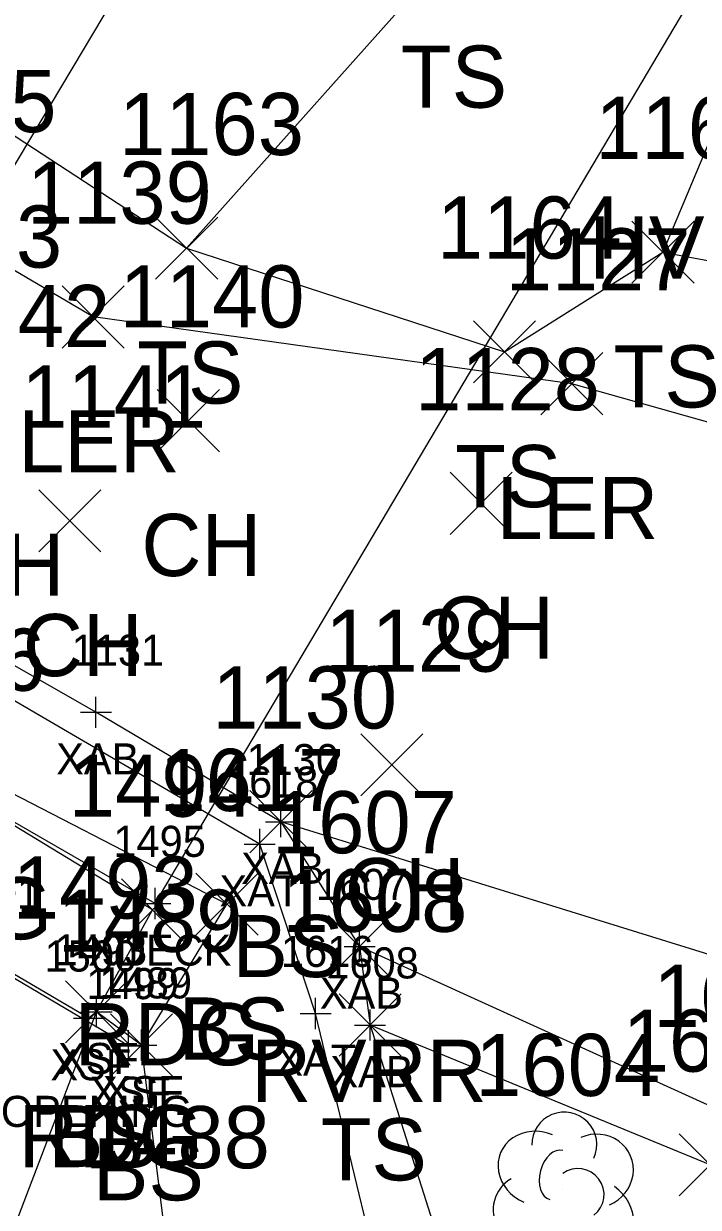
# Model space of a CAD drawing. Extents: x 1600281 to 1602254, y 862855 to 863227.
# Drawn here: x 1602044.06 to 1602065.77, y 863032.19 to 863070.29 of the extents above; entities that cross this region are included whole.
import ezdxf

# ---------------------------------------------------------------- set-up
doc = ezdxf.new("R2010")
doc.units = 0
for name, color, linetype in [('B_A', 7, 'Continuous'), ('B_C', 7, 'Continuous'), ('B_I', 7, 'Continuous'), ('B_TIC', 7, 'Continuous'), ('BDEFAULT', 7, 'Continuous'), ('BELB', 7, 'Continuous'), ('BSUBM', 7, 'Continuous'), ('C_A', 7, 'Continuous'), ('L_A', 7, 'Continuous'), ('L_I', 7, 'Continuous'), ('L_TIC', 7, 'Continuous'), ('LARO', 7, 'Continuous'), ('LAWE', 7, 'Continuous'), ('LELB', 7, 'Continuous'), ('LTD', 7, 'Continuous'), ('P_A', 7, 'Continuous'), ('P_I', 7, 'Continuous'), ('P_TIC', 7, 'Continuous'), ('PEU', 7, 'Continuous')]:
    doc.layers.add(name, color=color, linetype=linetype)

msp = doc.modelspace()

# ---------------------------------------------------------------- linework, layer by layer
at = {"layer": 'B_TIC'}
for p, q in [((1602046.387, 863048.124), (1602046.463, 863048.124)), ((1602052.341, 863044.601), (1602052.417, 863044.601)), ((1602052.341, 863044.601), (1602052.417, 863044.601)), ((1602051.658, 863043.876), (1602051.734, 863043.876)), ((1602048.296, 863041.97), (1602048.371, 863041.97)), ((1602048.296, 863041.97), (1602048.371, 863041.97)), ((1602054.871, 863040.585), (1602054.947, 863040.585)), ((1602046.162, 863038.279), (1602046.238, 863038.279)), ((1602046.405, 863038.482), (1602046.481, 863038.482)), ((1602053.456, 863038.428), (1602053.531, 863038.428)), ((1602055.21, 863038.057), (1602055.285, 863038.057)), ((1602047.853, 863037.414), (1602047.928, 863037.414)), ((1602047.853, 863037.414), (1602047.928, 863037.414)), ((1602047.434, 863037.391), (1602047.51, 863037.391))]:
    msp.add_line(p, q, dxfattribs=at)
for points in [[(1602046.384, 863047.624), (1602046.384, 863048.624)], [(1602045.884, 863048.124), (1602046.884, 863048.124)], [(1602052.338, 863044.101), (1602052.338, 863045.101)], [(1602052.338, 863044.101), (1602052.338, 863045.101)], [(1602051.655, 863043.376), (1602051.655, 863044.376)], [(1602051.838, 863044.601), (1602052.838, 863044.601)], [(1602051.838, 863044.601), (1602052.838, 863044.601)], [(1602051.155, 863043.876), (1602052.155, 863043.876)], [(1602048.292, 863041.47), (1602048.292, 863042.47)], [(1602048.292, 863041.47), (1602048.292, 863042.47)], [(1602047.792, 863041.97), (1602048.792, 863041.97)], [(1602047.792, 863041.97), (1602048.792, 863041.97)], [(1602054.868, 863040.085), (1602054.868, 863041.085)], [(1602054.368, 863040.585), (1602055.368, 863040.585)], [(1602046.402, 863037.982), (1602046.402, 863038.982)], [(1602053.452, 863037.928), (1602053.452, 863038.928)], [(1602046.159, 863037.779), (1602046.159, 863038.779)], [(1602055.206, 863037.557), (1602055.206, 863038.557)], [(1602045.659, 863038.279), (1602046.659, 863038.279)], [(1602045.902, 863038.482), (1602046.902, 863038.482)], [(1602052.952, 863038.428), (1602053.952, 863038.428)], [(1602047.431, 863036.891), (1602047.431, 863037.891)], [(1602047.849, 863036.914), (1602047.849, 863037.914)], [(1602047.849, 863036.914), (1602047.849, 863037.914)], [(1602054.706, 863038.057), (1602055.706, 863038.057)], [(1602047.349, 863037.414), (1602048.349, 863037.414)], [(1602047.349, 863037.414), (1602048.349, 863037.414)], [(1602046.931, 863037.391), (1602047.931, 863037.391)]]:
    msp.add_lwpolyline(points, dxfattribs=at)
at = {"layer": 'BDEFAULT'}
for points in [[(1602047.849, 863037.414), (1602047.431, 863037.391), (1602039.119, 863042.288), (1602030.822, 863047.255), (1602030.489, 863047.637)], [(1602047.849, 863037.414), (1602046.402, 863038.482), (1602046.159, 863038.279), (1602042.711, 863040.299), (1602035.646, 863044.498), (1602032.159, 863046.607), (1602032.199, 863046.614), (1602030.489, 863047.637)]]:
    msp.add_lwpolyline(points, dxfattribs=at)
at = {"layer": 'BELB'}
for points in [[(1602048.292, 863041.97), (1602034.377, 863049.991), (1602059.57, 863092.252), (1602073.185, 863083.996)], [(1602048.292, 863041.97), (1602073.185, 863083.996)]]:
    msp.add_lwpolyline(points, dxfattribs=at)
at = {"layer": 'BSUBM'}
for points in [[(1602052.338, 863044.601), (1602046.384, 863048.124), (1602041.512, 863050.909), (1602038.825, 863052.62), (1602034.084, 863055.493), (1602033.396, 863055.24), (1602030.833, 863052.803), (1602028.792, 863048.911)], [(1602055.512, 863025.783), (1602056.708, 863020.601), (1602057.448, 863021.08), (1602056.418, 863026.134), (1602053.452, 863038.428), (1602051.655, 863043.876), (1602033.283, 863054.61)], [(1602052.338, 863044.601), (1602054.868, 863040.585), (1602055.206, 863038.057), (1602057.929, 863029.474), (1602058.611, 863020.244), (1602056.322, 863019.422), (1602055.512, 863025.783)]]:
    msp.add_lwpolyline(points, dxfattribs=at)
at = {"layer": 'L_TIC'}
for points in [[(1602048.302, 863062.059), (1602050.302, 863064.059)], [(1602050.302, 863062.059), (1602048.302, 863064.059)], [(1602048.302, 863062.059), (1602050.302, 863064.059)], [(1602050.302, 863062.059), (1602048.302, 863064.059)], [(1602063.631, 863061.934), (1602065.631, 863063.934)], [(1602065.631, 863061.934), (1602063.631, 863063.934)], [(1602063.631, 863061.934), (1602065.631, 863063.934)], [(1602065.631, 863061.934), (1602063.631, 863063.934)], [(1602045.297, 863059.847), (1602047.297, 863061.847)], [(1602047.297, 863059.847), (1602045.297, 863061.847)], [(1602058.529, 863058.725), (1602060.529, 863060.725)], [(1602060.529, 863058.725), (1602058.529, 863060.725)], [(1602060.695, 863057.699), (1602062.695, 863059.699)], [(1602062.695, 863057.699), (1602060.695, 863059.699)], [(1602048.357, 863056.508), (1602050.357, 863058.508)], [(1602050.357, 863056.508), (1602048.357, 863058.508)], [(1602057.78, 863053.847), (1602059.78, 863055.847)], [(1602059.78, 863053.847), (1602057.78, 863055.847)], [(1602044.542, 863053.286), (1602046.542, 863055.286)], [(1602046.542, 863053.286), (1602044.542, 863055.286)], [(1602054.903, 863045.43), (1602056.903, 863047.43)], [(1602056.903, 863045.43), (1602054.903, 863047.43)], [(1602051.338, 863043.601), (1602053.338, 863045.601)], [(1602053.338, 863043.601), (1602051.338, 863045.601)], [(1602049.601, 863040.946), (1602051.601, 863042.946)], [(1602051.601, 863040.946), (1602049.601, 863042.946)], [(1602053.868, 863039.585), (1602055.868, 863041.585)], [(1602055.868, 863039.585), (1602053.868, 863041.585)], [(1602045.402, 863037.482), (1602047.402, 863039.482)], [(1602047.402, 863037.482), (1602045.402, 863039.482)], [(1602054.206, 863037.057), (1602056.206, 863039.057)], [(1602056.206, 863037.057), (1602054.206, 863039.057)], [(1602046.849, 863036.414), (1602048.849, 863038.414)], [(1602048.849, 863036.414), (1602046.849, 863038.414)], [(1602046.849, 863036.414), (1602048.849, 863038.414)], [(1602048.849, 863036.414), (1602046.849, 863038.414)], [(1602065.153, 863032.557), (1602067.153, 863034.557)], [(1602067.153, 863032.557), (1602065.153, 863034.557)]]:
    msp.add_lwpolyline(points, dxfattribs=at)
at = {"layer": 'LARO'}
msp.add_lwpolyline([(1602088.591, 863055.936), (1602084.205, 863057.115), (1602072.763, 863055.569), (1602061.695, 863058.699), (1602046.297, 863060.847), (1602041.29, 863063.794), (1602038.414, 863067.763), (1602029.525, 863077.549), (1602024.193, 863078.94), (1602013.468, 863079.959), (1602006.072, 863081.659), (1601997.978, 863081.824), (1601978.825, 863086.781)], dxfattribs=at)
at = {"layer": 'LAWE'}
msp.add_lwpolyline([(1602098.435, 862879.183), (1602097.38, 862900.93), (1602100.821, 862918.119), (1602111.897, 862945.191), (1602113.655, 862964.279), (1602114.598, 862983.415), (1602109.052, 863000.365), (1602100.599, 863011.379), (1602088.422, 863022.641), (1602086.169, 863023.524), (1602076.977, 863030.193), (1602067.142, 863034.999), (1602054.868, 863040.585)], dxfattribs=at)
at = {"layer": 'LELB'}
for points in [[(1602053.028, 863084.403), (1602044.996, 863082.199), (1602042.897, 863078.832), (1602038.461, 863076.466), (1602036.437, 863071.468), (1602049.302, 863063.059), (1602059.529, 863059.725), (1602064.631, 863062.934), (1602075.728, 863060.869), (1602085.918, 863063.754)], [(1602049.302, 863063.059), (1602057.788, 863072.582), (1602061.798, 863079.055)], [(1602069.576, 863074.729), (1602064.631, 863062.934)], [(1602047.849, 863037.414), (1602050.601, 863041.946), (1602032.716, 863051.177)], [(1602099.842, 862878.347), (1602100.95, 862904.784), (1602110.589, 862929.642), (1602115.654, 862954.701), (1602118.276, 862973.935), (1602116.239, 862983.386), (1602108.039, 863004.489), (1602102.906, 863010.993), (1602095.897, 863019.119), (1602089.354, 863024.498), (1602085.541, 863025.448), (1602074.55, 863034.496), (1602069.632, 863039.23), (1602052.338, 863044.601)], [(1602048.724, 863030.448), (1602047.849, 863037.414), (1602046.402, 863038.482)], [(1602075.62, 863029.355), (1602066.153, 863033.557), (1602055.206, 863038.057)]]:
    msp.add_lwpolyline(points, dxfattribs=at)
at = {"layer": 'LTD'}
msp.add_line((1602061.408, 863032.774), (1602061.408, 863032.774), dxfattribs=at)
msp.add_line((1602061.408, 863032.774), (1602061.408, 863032.774), dxfattribs=at)
msp.add_arc((1602061.455, 863034.208), 1.047, 335.5272, 180.9563, dxfattribs=at)
for centre, major_axis, ratio, start_param, end_param in [((1602060.616, 863033.44), (1.21, -0.512), 0.895232, 1.570796, 4.712389), ((1602062.449, 863033.357), (-1.141, -0.483), 0.949671, 1.570796, 4.712389), ((1602061.199, 863033.232), (-0.208, -0.792), 0.645439, 3.141593, 6.283185), ((1602061.908, 863032.607), (-0.5, 0.667), 0.989748, 3.141593, 6.283185), ((1602060.325, 863032.065), (0.584, -1.042), 0.959034, 3.141593, 6.283185), ((1602062.408, 863031.94), (-1.09, 0.792), 0.841452, 1.570796, 4.712389)]:
    msp.add_ellipse(centre, major_axis=major_axis, ratio=ratio, start_param=start_param, end_param=end_param, dxfattribs=at)
at = {"layer": 'P_TIC'}
for points in [[(1602047.205, 863040.762), (1602049.205, 863042.762)], [(1602049.205, 863040.762), (1602047.205, 863042.762)], [(1602045.402, 863037.482), (1602047.402, 863039.482)], [(1602047.402, 863037.482), (1602045.402, 863039.482)]]:
    msp.add_lwpolyline(points, dxfattribs=at)
at = {"layer": 'PEU'}
msp.add_lwpolyline([(1601721.431, 862942.479), (1601759.391, 862940.415), (1601795.476, 862935.046), (1601824.436, 862931.284), (1601871.597, 862925.252), (1601900.947, 862923.392), (1601930.539, 862915.155), (1601956.45, 862910.483), (1601973.532, 862907.721), (1601992.866, 862904.836), (1602011.433, 862910.06), (1602025.54, 862921.56), (1602034.602, 862951.409), (1602037.167, 862973.137), (1602036.63, 863000.366), (1602039.384, 863008.705), (1602041.945, 863026.807), (1602046.402, 863038.482), (1602048.205, 863041.762), (1602041.548, 863045.817), (1602034.191, 863049.728), (1602032.199, 863046.614)], dxfattribs=at)

# ---------------------------------------------------------------- texts
at = {"layer": 'B_A'}
for s, p in [('XAB', (1602045.104, 863046.124)), ('XAB', (1602051.058, 863042.601)), ('XAB', (1602051.058, 863042.601)), ('XAT', (1602050.359, 863041.876)), ('XDECK', (1602046.135, 863039.97)), ('XDECK', (1602046.135, 863039.97)), ('XAB', (1602053.588, 863038.585)), ('XSF', (1602045.162, 863036.482)), ('XAT', (1602052.157, 863036.428)), ('XSF', (1602044.919, 863036.279)), ('XAB', (1602053.927, 863036.057)), ('XSF', (1602046.19, 863035.391)), ('XSF', (1602046.609, 863035.414)), ('XSF', (1602046.609, 863035.414))]:
    msp.add_text(s, height=1, dxfattribs=at).set_placement(p)
at = {"layer": 'B_C'}
msp.add_text('OPENING', height=1, dxfattribs=at).set_placement((1602043.328, 863034.779))
at = {"layer": 'B_I'}
for s, p in [('1131', (1602045.604, 863049.624)), ('1130', (1602051.232, 863046.101)), ('1130', (1602051.232, 863046.101)), ('1618', (1602050.568, 863045.376)), ('1495', (1602046.946, 863043.47)), ('1495', (1602046.946, 863043.47)), ('1501', (1602041.609, 863041.799)), ('1607', (1602053.458, 863042.085)), ('1493', (1602045.055, 863039.982)), ('1616', (1602052.338, 863039.928)), ('1500', (1602044.73, 863039.779)), ('1608', (1602053.797, 863039.557)), ('1499', (1602046.08, 863038.891)), ('1489', (1602046.499, 863038.914)), ('1489', (1602046.499, 863038.914))]:
    msp.add_text(s, height=1, dxfattribs=at).set_placement(p)
at = {"layer": 'C_A'}
msp.add_text('HVCTRL', height=2, dxfattribs=at).set_placement((1602062.251, 863062.081))
at = {"layer": 'L_A'}
for s, p in [('TS', (1602056.197, 863067.582)), ('TS', (1602047.711, 863058.059)), ('TS', (1602047.711, 863058.059)), ('TS', (1602063.041, 863057.934)), ('TS', (1602063.041, 863057.934)), ('LER', (1602043.879, 863055.847)), ('TS', (1602057.938, 863054.725)), ('LER', (1602059.278, 863053.699)), ('CH', (1602047.845, 863052.508)), ('CH', (1602041.508, 863051.877)), ('CH', (1602057.268, 863049.847)), ('CH', (1602044.03, 863049.286)), ('CH', (1602054.391, 863041.43)), ('BS', (1602050.779, 863039.601)), ('BS', (1602049.042, 863036.946)), ('RVRR', (1602051.38, 863035.585)), ('BS', (1602044.843, 863033.482)), ('TS', (1602053.615, 863033.057)), ('BS', (1602046.29, 863032.414)), ('BS', (1602046.29, 863032.414))]:
    msp.add_text(s, height=2, dxfattribs=at).set_placement(p)
at = {"layer": 'L_I'}
for s, p in [('1145', (1602039.164, 863066.794)), ('1163', (1602047.129, 863066.059)), ('1163', (1602047.129, 863066.059)), ('1169', (1602062.45, 863065.934)), ('1169', (1602062.45, 863065.934)), ('1139', (1602044.163, 863063.847)), ('1143', (1602039.349, 863062.435)), ('1164', (1602057.356, 863062.725)), ('1127', (1602059.569, 863061.699)), ('1140', (1602047.145, 863060.508)), ('1142', (1602040.894, 863059.877)), ('1128', (1602056.654, 863057.847)), ('1141', (1602043.983, 863057.286)), ('1129', (1602053.769, 863049.43)), ('1130', (1602050.125, 863047.601)), ('1617', (1602048.427, 863044.946)), ('1607', (1602052.049, 863043.585)), ('1493', (1602043.709, 863041.482)), ('1608', (1602052.387, 863041.057)), ('1489', (1602045.148, 863040.414)), ('1489', (1602045.148, 863040.414)), ('1602', (1602064.323, 863037.999)), ('1603', (1602063.334, 863036.557)), ('1604', (1602058.589, 863035.774)), ('1488', (1602046.031, 863033.448)), ('1488', (1602046.031, 863033.448))]:
    msp.add_text(s, height=2, dxfattribs=at).set_placement(p)
at = {"layer": 'P_A'}
for p in [(1602039.036, 863040.817), (1602045.694, 863036.762), (1602043.89, 863033.482)]:
    msp.add_text('RDG', height=2, dxfattribs=at).set_placement(p)
at = {"layer": 'P_I'}
for s, p in [('1496', (1602038.8, 863048.817)), ('1496', (1602038.8, 863048.817)), ('1494', (1602045.512, 863044.762)), ('1493', (1602043.709, 863041.482))]:
    msp.add_text(s, height=2, dxfattribs=at).set_placement(p)

doc.saveas('drawing.dxf')
